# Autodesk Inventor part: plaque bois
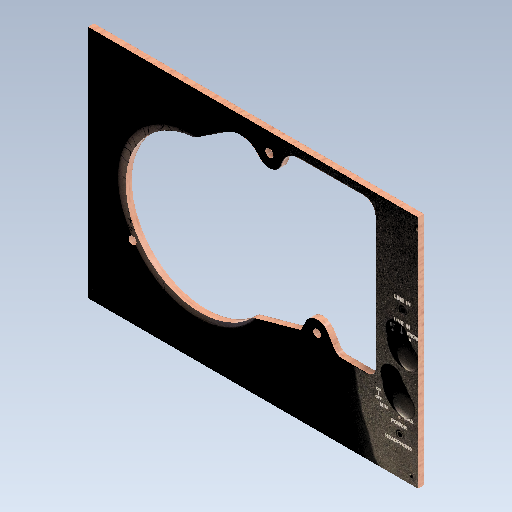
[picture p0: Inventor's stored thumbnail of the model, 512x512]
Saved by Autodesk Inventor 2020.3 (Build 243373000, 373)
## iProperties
Created: 2020-09
Part Number: plaque bois
Material: Bois (Chêne)
Document SubType Name: Modeling
Designer: ficho
Density: 0.76 g/cm^3
Appearance: Chêne blanc - Lustre moyen naturel
Mass: 194.55 g
Surface Area: 972.331 cm^2
Volume: 255.987 cm^3
Author: ficho
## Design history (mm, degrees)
sketch "Esquisse1"
  geometry: L1 (0, 0)-(-330, 0); L2 (-330, 0)-(-330, 235); L3 (-330, 235)-(0, 235); L4 (0, 235)-(0, 0)
  constraints: 8 end point, 2 parallel, 1 horizontal, 1 perpendicular
  dimensions: "d0" = 330 distance of L2.end L3.end; "d1" = 235 distance of L1.end L2.end
extrude "Extrusion1" new body sketch "Esquisse1" distance "d2" = 6; taper "d3" = 0 deg
sketch "Esquisse2"
  geometry: L1 (-459.857, 247.736)-(117.786, 252.895); L2 (117.786, 252.895)-(120.151, -11.857); L3 (120.151, -11.857)-(-457.492, -17.017); L4 (-457.492, -17.017)-(-459.857, 247.736); 1 further point; 1 other entity
  constraints: 2 other
feature "Décalcomanie1" sketch "Esquisse2"
sketch "Esquisse3"
  geometry: L1 (-134.608, 213.236)-(-134.608, 213.236); L2 (-134.957, 215.802)-(-136.321, 211.962); L3 (-119.715, 226.634)-(-54.813, 227.044); L4 (-42.242, 214.553)-(-42.242, 82.69); L5 (-50.186, 74.745)-(-76.051, 74.745); L6 (-83.198, 78.732)-(-90.461, 90.498); L7 (-164.764, 65.66)-(-117.359, 78.732) reference; L8 (-111.728, 89.672)-(-117.359, 78.732); L9 (-190.497, 213.95)-(-223.277, 192.443) reference; C1 r 4 at (-148.736, 216.373); C2 r 4 at (-100.861, 84.078); C3 r 4 at (-285.43, 72.196); A1 r 13.175 centre (-148.736, 216.373) between (-159.281, 208.475) and (-136.321, 211.962); A2 r 16.284 centre (-119.612, 210.35) between (-119.715, 226.634) and (-134.957, 215.802); A3 r 12.491 centre (-54.734, 214.553) between (-42.242, 214.553) and (-54.813, 227.044); A4 r 7.944 centre (-50.186, 82.69) between (-50.186, 74.745) and (-42.242, 82.69); A5 r 12.222 centre (-100.861, 84.078) between (-90.461, 90.498) and (-111.728, 89.672); A6 r 8.399 centre (-76.051, 83.144) between (-83.198, 78.732) and (-76.051, 74.745); A7 r 23.141 centre (-177.802, 194.603) between (-159.281, 208.475) and (-190.497, 213.95); A8 r 74.546 centre (-217.745, 118.102) between (-223.277, 192.443) and (-164.764, 65.66); 1 further point
  constraints: 18 end point, 16 point on circle, 13 tangent, 11 centre point, 2 coincident, 1 horizontal, 1 vertical, 2 other
  dimensions: "d29" = 8 diameter of C1; "d30" = 8 diameter of C2; "d31" = 8 diameter of C3
extrude "Extrusion2" cut sketch "Esquisse3" distance "d32" = 8 (= d29); taper "d33" = 0 deg
node "Solide1"
node "Image1"
